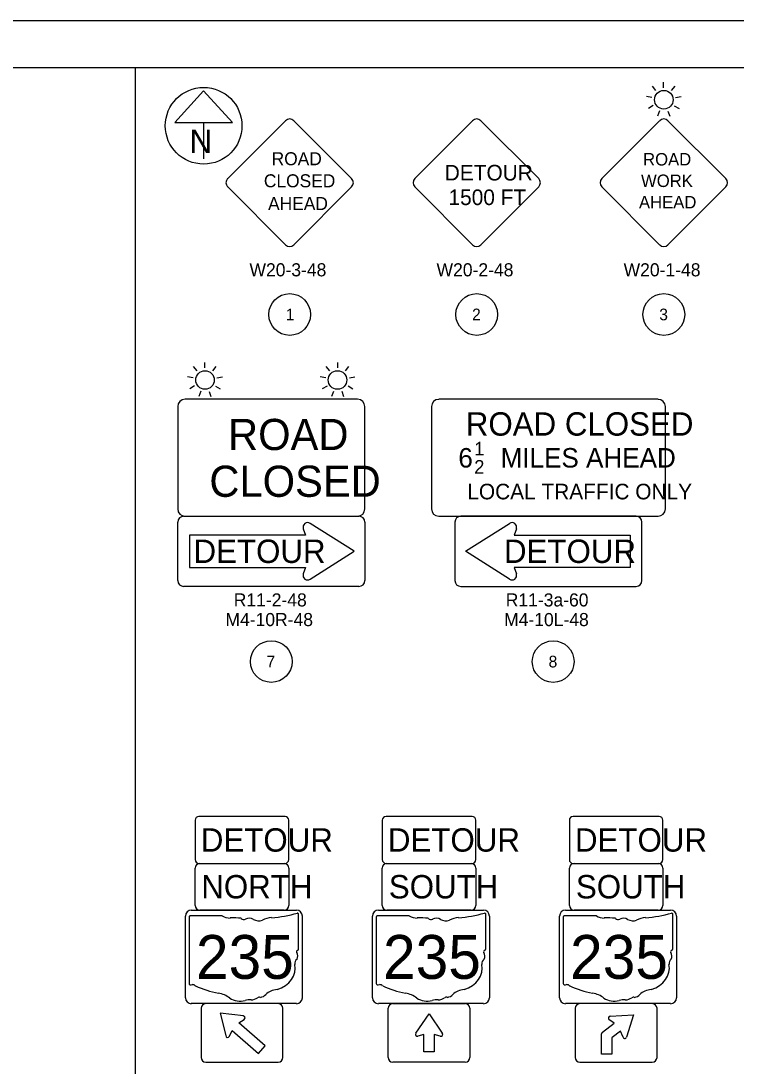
# Model space of a CAD drawing. Extents: x 632.2 to 666.2, y -36.3 to -14.3.
# Drawn here: x 649.19 to 656.83, y -25.48 to -14.3 of the extents above; entities that cross this region are included whole.
import ezdxf

# ---------------------------------------------------------------- set-up
doc = ezdxf.new("R2010")
doc.units = 0
for name, color, linetype in [('Default', 7, 'Continuous'), ('MT_P_Cells', 7, 'Continuous'), ('SH_Border', 7, 'Continuous'), ('SH_Cut_Line', 7, 'Continuous'), ('SH_Masking', 7, 'Continuous'), ('SH_Text', 7, 'Continuous'), ('SN_P_Signs', 7, 'Continuous'), ('SN_P_Text', 7, 'Continuous')]:
    doc.layers.add(name, color=color, linetype=linetype)

msp = doc.modelspace()

# ---------------------------------------------------------------- linework, layer by layer
at = {"layer": 'Default'}
for centre in [(652.061, -17.441), (654.061, -17.441), (656.061, -17.441), (651.864, -21.151), (654.878, -21.151)]:
    msp.add_circle(centre, 0.223, dxfattribs=at)
at = {"layer": 'MT_P_Cells'}
for p, q in [((656.059, -15.016), (656.059, -14.956)), ((655.977, -15.046), (655.939, -15.001)), ((656.143, -15.045), (656.181, -14.999)), ((655.934, -15.122), (655.875, -15.112)), ((656.187, -15.122), (656.246, -15.111)), ((655.948, -15.208), (655.897, -15.238)), ((656.015, -15.265), (655.995, -15.321)), ((656.104, -15.266), (656.124, -15.322)), ((656.172, -15.209), (656.224, -15.239)), ((651.154, -18.012), (651.154, -17.953)), ((652.574, -18.012), (652.574, -17.953)), ((651.072, -18.043), (651.034, -17.998)), ((651.238, -18.042), (651.276, -17.996)), ((652.491, -18.042), (652.452, -17.996)), ((652.656, -18.043), (652.694, -17.998)), ((651.029, -18.119), (650.97, -18.109)), ((651.043, -18.205), (650.992, -18.235)), ((651.267, -18.206), (651.319, -18.236)), ((651.282, -18.118), (651.341, -18.108)), ((652.446, -18.118), (652.387, -18.108)), ((652.461, -18.206), (652.41, -18.236)), ((652.685, -18.205), (652.736, -18.235)), ((652.699, -18.119), (652.758, -18.109)), ((651.11, -18.262), (651.09, -18.318)), ((651.199, -18.263), (651.219, -18.319)), ((652.529, -18.263), (652.509, -18.319)), ((652.618, -18.262), (652.638, -18.318))]:
    msp.add_line(p, q, dxfattribs=at)
for centre in [(656.061, -15.145), (651.156, -18.141), (652.572, -18.141)]:
    msp.add_circle(centre, 0.0992, dxfattribs=at)
at = {"layer": 'SH_Border'}
msp.add_lwpolyline([(633.687, -14.802), (665.687, -14.802), (665.687, -35.802), (633.687, -35.802)], close=True, dxfattribs=at)
at = {"layer": 'SH_Cut_Line'}
msp.add_lwpolyline([(632.187, -36.302), (666.187, -36.302), (666.187, -14.302), (632.187, -14.302)], close=True, dxfattribs=at)
at = {"layer": 'SH_Masking'}
msp.add_circle((651.141, -15.423), 0.41, dxfattribs=at)
at = {"layer": 'SH_Text'}
for p, q in [((650.412, -35.802), (650.412, -14.802)), ((651.141, -15.049), (650.833, -15.39)), ((651.449, -15.39), (651.141, -15.049)), ((650.833, -15.39), (651.449, -15.39)), ((651.141, -15.39), (651.141, -15.777))]:
    msp.add_line(p, q, dxfattribs=at)
for points in [[(651.398, -15.988), (652.016, -15.369)], [(652.105, -15.369), (652.723, -15.988)], [(652.016, -16.695), (651.398, -16.076)], [(652.723, -16.076), (652.105, -16.695)]]:
    msp.add_lwpolyline(points, dxfattribs=at)
msp.add_circle((651.141, -15.423), 0.41, dxfattribs=at)
for centre, start, end in [((652.061, -15.413), 45, 135), ((651.442, -16.032), 135, 225), ((652.679, -16.032), 315, 45), ((652.061, -16.651), 225, 315)]:
    msp.add_arc(centre, 0.0625, start, end, dxfattribs=at)
at = {"layer": 'SN_P_Signs'}
for p, q in [((652.206, -19.731), (652.229, -19.801)), ((652.749, -19.972), (652.281, -19.674)), ((653.942, -19.972), (654.41, -19.674)), ((654.485, -19.731), (654.462, -19.801)), ((652.229, -19.801), (650.989, -19.801)), ((650.989, -19.801), (650.989, -20.144)), ((654.462, -19.801), (655.702, -19.801)), ((655.702, -19.801), (655.702, -20.144)), ((652.281, -20.271), (652.749, -19.972)), ((654.41, -20.271), (653.942, -19.972)), ((650.989, -20.144), (652.229, -20.144)), ((652.229, -20.144), (652.206, -20.214)), ((655.702, -20.144), (654.462, -20.144)), ((654.462, -20.144), (654.485, -20.214)), ((651.101, -23.308), (652.001, -23.308)), ((653.101, -23.308), (654.001, -23.308)), ((655.101, -23.308), (656.001, -23.308)), ((651.051, -23.758), (651.051, -23.358)), ((652.051, -23.358), (652.051, -23.758)), ((653.051, -23.758), (653.051, -23.358)), ((654.051, -23.358), (654.051, -23.758)), ((655.051, -23.758), (655.051, -23.358)), ((656.051, -23.358), (656.051, -23.758)), ((650.985, -23.882), (650.985, -24.594)), ((651.34, -23.87), (650.997, -23.87)), ((652.001, -23.808), (651.101, -23.808)), ((652.157, -24.224), (652.157, -23.852)), ((652.985, -23.882), (652.985, -24.594)), ((653.34, -23.87), (652.997, -23.87)), ((654.001, -23.808), (653.101, -23.808)), ((654.157, -24.224), (654.157, -23.852)), ((654.985, -23.882), (654.985, -24.594)), ((655.34, -23.87), (654.997, -23.87)), ((656.001, -23.808), (655.101, -23.808)), ((656.157, -24.224), (656.157, -23.852)), ((652.157, -24.224), (652.157, -24.224)), ((654.157, -24.224), (654.157, -24.224)), ((656.157, -24.224), (656.157, -24.224)), ((651.113, -24.858), (651.113, -25.383)), ((651.938, -24.808), (651.163, -24.808)), ((651.566, -24.94), (651.316, -24.91)), ((651.316, -24.91), (651.377, -25.15)), ((651.988, -25.383), (651.988, -24.858)), ((653.113, -25.383), (653.113, -24.858)), ((653.163, -24.808), (653.938, -24.808)), ((653.988, -24.858), (653.988, -25.383)), ((655.113, -24.858), (655.113, -25.383)), ((655.938, -24.808), (655.163, -24.808)), ((655.988, -25.383), (655.988, -24.858)), ((651.517, -25.013), (651.574, -24.978)), ((651.798, -25.26), (651.517, -25.013)), ((651.566, -24.94), (651.566, -24.94)), ((653.408, -25.125), (653.551, -24.918)), ((653.551, -24.918), (653.69, -25.122)), ((655.404, -25.114), (655.53, -25.015)), ((655.53, -25.015), (655.474, -24.977)), ((655.488, -24.942), (655.738, -24.926)), ((655.488, -24.942), (655.488, -24.942)), ((655.738, -24.926), (655.663, -25.166)), ((651.417, -25.157), (651.445, -25.095)), ((651.445, -25.095), (651.726, -25.342)), ((653.496, -25.137), (653.432, -25.157)), ((653.496, -25.324), (653.496, -25.137)), ((653.669, -25.157), (653.605, -25.137)), ((653.605, -25.137), (653.605, -25.324)), ((655.394, -25.348), (655.394, -25.132)), ((655.597, -25.101), (655.51, -25.17)), ((655.622, -25.16), (655.597, -25.101)), ((655.504, -25.182), (655.504, -25.348)), ((651.726, -25.342), (651.798, -25.26)), ((653.605, -25.324), (653.496, -25.324)), ((655.504, -25.348), (655.394, -25.348)), ((651.163, -25.433), (651.938, -25.433)), ((653.938, -25.433), (653.163, -25.433)), ((655.163, -25.433), (655.938, -25.433))]:
    msp.add_line(p, q, dxfattribs=at)
for points in [[(653.398, -15.988), (654.016, -15.369)], [(654.105, -15.369), (654.723, -15.988)], [(655.398, -15.988), (656.016, -15.369)], [(656.105, -15.369), (656.723, -15.988)], [(654.016, -16.695), (653.398, -16.076)], [(654.723, -16.076), (654.105, -16.695)], [(656.016, -16.695), (655.398, -16.076)], [(656.723, -16.076), (656.105, -16.695)], [(650.864, -18.426), (650.864, -19.519)], [(652.786, -18.347), (650.942, -18.347)], [(652.864, -19.519), (652.864, -18.426)], [(653.577, -18.426), (653.577, -19.519)], [(655.999, -18.347), (653.655, -18.347)], [(656.077, -19.519), (656.077, -18.426)], [(650.864, -20.285), (650.864, -19.66)], [(650.927, -19.597), (652.802, -19.597)], [(650.942, -19.597), (652.786, -19.597)], [(652.864, -19.66), (652.864, -20.285)], [(653.655, -19.597), (655.999, -19.597)], [(653.827, -19.66), (653.827, -20.285)], [(655.765, -19.597), (653.89, -19.597)], [(655.827, -20.285), (655.827, -19.66)], [(652.802, -20.347), (650.927, -20.347)], [(653.89, -20.347), (655.765, -20.347)], [(651.051, -22.848), (651.051, -23.268)], [(652.011, -22.808), (651.091, -22.808)], [(652.051, -23.268), (652.051, -22.848)], [(653.051, -22.848), (653.051, -23.268)], [(654.011, -22.808), (653.091, -22.808)], [(654.051, -23.268), (654.051, -22.848)], [(655.051, -22.848), (655.051, -23.268)], [(656.011, -22.808), (655.091, -22.808)], [(656.051, -23.268), (656.051, -22.848)], [(651.091, -23.308), (652.011, -23.308)], [(653.091, -23.308), (654.011, -23.308)], [(655.091, -23.308), (656.011, -23.308)], [(650.946, -24.746), (650.946, -23.871)], [(651.009, -23.808), (652.134, -23.808)], [(652.196, -23.871), (652.196, -24.746)], [(652.946, -24.746), (652.946, -23.871)], [(653.009, -23.808), (654.134, -23.808)], [(654.196, -23.871), (654.196, -24.746)], [(654.946, -24.746), (654.946, -23.871)], [(655.009, -23.808), (656.134, -23.808)], [(656.196, -23.871), (656.196, -24.746)], [(652.134, -24.808), (651.009, -24.808)], [(654.134, -24.808), (653.009, -24.808)], [(656.134, -24.808), (655.009, -24.808)]]:
    msp.add_lwpolyline(points, dxfattribs=at)
for centre, radius, start, end in [((654.061, -15.413), 0.0625, 45, 135), ((656.061, -15.413), 0.0625, 45, 135), ((653.442, -16.032), 0.0625, 135, 225), ((654.679, -16.032), 0.0625, 315, 45), ((655.442, -16.032), 0.0625, 135, 225), ((656.679, -16.032), 0.0625, 315, 45), ((654.061, -16.651), 0.0625, 225, 315), ((656.061, -16.651), 0.0625, 225, 315), ((650.942, -18.426), 0.0783, 90, 180), ((652.786, -18.426), 0.0783, 0, 90), ((653.655, -18.426), 0.0781, 90, 180), ((655.999, -18.426), 0.0781, 0, 90), ((650.942, -19.519), 0.0783, 180, 270), ((652.786, -19.519), 0.0783, 270, 0), ((653.655, -19.519), 0.0781, 180, 270), ((655.999, -19.519), 0.0781, 270, 0), ((650.927, -19.66), 0.0625, 90, 180), ((652.802, -19.66), 0.0625, 0, 90), ((653.89, -19.66), 0.0625, 90, 180), ((655.765, -19.66), 0.0625, 0, 90), ((652.254, -19.716), 0.05, 57.4891, 197.8189), ((654.437, -19.716), 0.05, 342.1811, 122.5109), ((652.254, -20.229), 0.05, 162.1811, 302.5109), ((654.437, -20.229), 0.05, 237.4891, 17.8189), ((650.927, -20.285), 0.0625, 180, 270), ((652.802, -20.285), 0.0625, 270, 360), ((653.89, -20.285), 0.0625, 180, 270), ((655.765, -20.285), 0.0625, 270, 0), ((651.091, -22.848), 0.04, 90, 180), ((652.011, -22.848), 0.04, 0, 90), ((653.091, -22.848), 0.04, 90, 180), ((654.011, -22.848), 0.04, 0, 90), ((655.091, -22.848), 0.04, 90, 180), ((656.011, -22.848), 0.04, 0, 90), ((651.091, -23.268), 0.04, 180, 270), ((651.101, -23.358), 0.05, 90, 180), ((652.001, -23.358), 0.05, 0, 90), ((652.011, -23.268), 0.04, 270, 0), ((653.091, -23.268), 0.04, 180, 270), ((653.101, -23.358), 0.05, 90, 180), ((654.001, -23.358), 0.05, 0, 90), ((654.011, -23.268), 0.04, 270, 0), ((655.091, -23.268), 0.04, 180, 270), ((655.101, -23.358), 0.05, 90, 180), ((656.001, -23.358), 0.05, 0, 90), ((656.011, -23.268), 0.04, 270, 0), ((651.101, -23.758), 0.05, 180, 270), ((652.001, -23.758), 0.05, 270, 0), ((653.101, -23.758), 0.05, 180, 270), ((654.001, -23.758), 0.05, 270, 0), ((655.101, -23.758), 0.05, 180, 270), ((656.001, -23.758), 0.05, 270, 0), ((651.009, -23.871), 0.0625, 90, 180), ((652.134, -23.871), 0.0625, 0, 90), ((653.009, -23.871), 0.0625, 90, 180), ((654.134, -23.871), 0.0625, 0, 90), ((655.009, -23.871), 0.0625, 90, 180), ((656.134, -23.871), 0.0625, 0, 90), ((651.009, -24.746), 0.0625, 180, 270), ((652.134, -24.746), 0.0625, 270, 0), ((653.009, -24.746), 0.0625, 180, 270), ((654.134, -24.746), 0.0625, 270, 0), ((655.009, -24.746), 0.0625, 180, 270), ((656.134, -24.746), 0.0625, 270, 0), ((651.163, -24.858), 0.05, 90, 180), ((651.938, -24.858), 0.05, 0, 90), ((653.163, -24.858), 0.05, 90, 180), ((653.938, -24.858), 0.05, 0, 90), ((655.163, -24.858), 0.05, 90, 180), ((655.938, -24.858), 0.05, 0, 90), ((651.563, -24.96), 0.0208, 301.5367, 83.3301), ((655.489, -24.963), 0.0209, 93.5999, 225.0001), ((653.426, -25.137), 0.0209, 145.4112, 287.2046), ((653.676, -25.137), 0.0209, 252.7954, 45.0096), ((655.418, -25.132), 0.0234, 127.7857, 180), ((651.398, -25.148), 0.0208, 183.7317, 335.9459), ((655.519, -25.182), 0.0156, 127.3494, 180), ((655.643, -25.16), 0.0209, 180.0509, 342.5804), ((651.163, -25.383), 0.05, 180, 270), ((651.938, -25.383), 0.05, 270, 360), ((653.163, -25.383), 0.05, 180, 270), ((653.938, -25.383), 0.05, 270, 0), ((655.163, -25.383), 0.05, 180, 270), ((655.938, -25.383), 0.05, 270, 360)]:
    msp.add_arc(centre, radius, start, end, dxfattribs=at)
for centre, major_axis, start_param, end_param in [((650.999, -23.881), (0.0136, 0), 1.712693, 3.28349), ((651.422, -23.787), (0.132, 0), 4.042523, 4.731795), ((651.465, -24.269), (0.473, 0), 1.404758, 1.657858), ((651.573, -23.877), (0.038, 0), 3.836095, 5.185415), ((651.628, -23.959), (0.079, 0), 0.950623, 2.079405), ((651.73, -23.846), (0.095, 0), 4.081561, 5.145723), ((651.898, -24.087), (0.25, 0), 1.699011, 2.107814), ((651.74, -22.9), (1.243, 0), 4.814394, 5.042369), ((652.144, -23.851), (0.013, 0), 6.141152, 7.989035), ((652.999, -23.881), (0.0136, 0), 1.712693, 3.28349), ((653.422, -23.787), (0.132, 0), 4.042523, 4.731795), ((653.465, -24.269), (0.473, 0), 1.404758, 1.657858), ((653.573, -23.877), (0.038, 0), 3.836095, 5.185415), ((653.628, -23.959), (0.079, 0), 0.950623, 2.079405), ((653.73, -23.846), (0.095, 0), 4.081561, 5.145723), ((653.898, -24.087), (0.25, 0), 1.699011, 2.107814), ((653.74, -22.9), (1.243, 0), 4.814394, 5.042369), ((654.144, -23.851), (0.013, 0), 6.141152, 7.989035), ((654.999, -23.881), (0.0136, 0), 1.712693, 3.28349), ((655.422, -23.787), (0.132, 0), 4.042523, 4.731795), ((655.465, -24.269), (0.473, 0), 1.404758, 1.657858), ((655.573, -23.877), (0.038, 0), 3.836095, 5.185415), ((655.628, -23.959), (0.079, 0), 0.950623, 2.079405), ((655.73, -23.846), (0.095, 0), 4.081561, 5.145723), ((655.898, -24.087), (0.25, 0), 1.699011, 2.107814), ((655.74, -22.9), (1.243, 0), 4.814394, 5.042369), ((656.144, -23.851), (0.013, 0), 6.141152, 7.989035), ((652.154, -24.252), (0.0202, 0), 1.883978, 3.671073), ((652.143, -24.226), (0.014, 0), 5.05454, 6.418171), ((654.154, -24.252), (0.0202, 0), 1.883978, 3.671073), ((654.143, -24.226), (0.014, 0), 5.05454, 6.418171), ((656.154, -24.252), (0.0202, 0), 1.883978, 3.671073), ((656.143, -24.226), (0.014, 0), 5.05454, 6.418171), ((652.204, -24.38), (0.0882, 0), 2.387724, 3.262537), ((652.026, -24.299), (0.121, 0), 5.934695, 6.695948), ((654.204, -24.38), (0.0882, 0), 2.387724, 3.262537), ((654.026, -24.299), (0.121, 0), 5.934695, 6.695948), ((656.204, -24.38), (0.0882, 0), 2.387724, 3.262537), ((656.026, -24.299), (0.121, 0), 5.934695, 6.695948), ((651.809, -24.428), (0.311, 0), 5.101752, 6.440018), ((653.809, -24.428), (0.311, 0), 5.101752, 6.440018), ((655.809, -24.428), (0.311, 0), 5.101752, 6.440018), ((650.999, -24.595), (0.0137, 0), 3.00124, 4.508301), ((651.001, -24.522), (0.105, 0), 4.665946, 4.897461), ((651.022, -24.635), (0.0377, 0), 0.519207, 1.627899), ((651.498, -23.995), (0.897, 0), 4.195997, 4.488961), ((651.94, -24.793), (0.17, 0), 1.647645, 2.488434), ((652.999, -24.595), (0.0137, 0), 3.00124, 4.508301), ((653.001, -24.522), (0.105, 0), 4.665946, 4.897461), ((653.022, -24.635), (0.0377, 0), 0.519207, 1.627899), ((653.498, -23.995), (0.897, 0), 4.195997, 4.488961), ((653.94, -24.793), (0.17, 0), 1.647645, 2.488434), ((654.999, -24.595), (0.0137, 0), 3.00124, 4.508301), ((655.001, -24.522), (0.105, 0), 4.665946, 4.897461), ((655.022, -24.635), (0.0377, 0), 0.519207, 1.627899), ((655.498, -23.995), (0.897, 0), 4.195997, 4.488961), ((655.94, -24.793), (0.17, 0), 1.647645, 2.488434), ((651.23, -24.913), (0.281, 0), 0.823519, 1.323587), ((651.534, -24.638), (0.178, 0), 4.026481, 4.996735), ((651.637, -24.884), (0.146, 0), 1.495662, 1.94098), ((651.65, -24.691), (0.0949, 0), 4.691044, 5.507374), ((651.736, -24.76), (0.0267, 0), 1.147584, 2.315152), ((651.725, -24.663), (0.1, 0), 4.937069, 5.64225), ((653.23, -24.913), (0.281, 0), 0.823519, 1.323587), ((653.534, -24.638), (0.178, 0), 4.026481, 4.996735), ((653.637, -24.884), (0.146, 0), 1.495662, 1.94098), ((653.65, -24.691), (0.0949, 0), 4.691044, 5.507374), ((653.736, -24.76), (0.0267, 0), 1.147584, 2.315152), ((653.725, -24.663), (0.1, 0), 4.937069, 5.64225), ((655.23, -24.913), (0.281, 0), 0.823519, 1.323587), ((655.534, -24.638), (0.178, 0), 4.026481, 4.996735), ((655.637, -24.884), (0.146, 0), 1.495662, 1.94098), ((655.65, -24.691), (0.0949, 0), 4.691044, 5.507374), ((655.736, -24.76), (0.0267, 0), 1.147584, 2.315152), ((655.725, -24.663), (0.1, 0), 4.937069, 5.64225)]:
    msp.add_ellipse(centre, major_axis=major_axis, ratio=0.8, start_param=start_param, end_param=end_param, dxfattribs=at)

# ---------------------------------------------------------------- texts
at = {"layer": 'Default'}
for s, p in [('1', (652.019, -17.503)), ('2', (654.011, -17.503)), ('3', (656.012, -17.503)), ('7', (651.812, -21.214)), ('8', (654.829, -21.214))]:
    msp.add_text(s, height=0.125, dxfattribs=at).set_placement(p)
at = {"layer": 'SH_Text'}
for s, height, p in [('N', 0.25, (650.99, -15.714)), ('ROAD', 0.1389, (651.868, -15.845)), ('CLOSED', 0.1389, (651.785, -16.081)), ('AHEAD', 0.1389, (651.83, -16.324))]:
    msp.add_text(s, height=height, dxfattribs=at).set_placement(p)
at = {"layer": 'SN_P_Signs'}
for s, height, p in [('ROAD', 0.1333, (655.839, -15.848)), ('DETOUR', 0.1667, (653.719, -16.008)), ('WORK', 0.1333, (655.817, -16.078)), ('1500 FT', 0.1667, (653.759, -16.271)), ('AHEAD', 0.1333, (655.795, -16.307)), ('ROAD CLOSED', 0.25, (653.944, -18.736)), ('ROAD', 0.3333, (651.402, -18.89)), ('6 ', 0.2083, (653.864, -19.077)), ('1', 0.146, (654.034, -18.948)), ('MILES AHEAD', 0.20833, (654.316, -19.077)), ('CLOSED', 0.3333, (651.202, -19.39)), ('2', 0.146, (654.034, -19.143)), ('LOCAL TRAFFIC ONLY', 0.16667, (653.96, -19.417)), ('DETOUR', 0.25, (651.033, -20.097)), ('DETOUR', 0.25, (654.352, -20.097)), ('DETOUR', 0.25, (651.111, -23.183)), ('DETOUR', 0.25, (653.111, -23.183)), ('DETOUR', 0.25, (655.111, -23.183)), ('NORTH', 0.25, (651.116, -23.683)), ('SOUTH', 0.25, (653.121, -23.683)), ('SOUTH', 0.25, (655.121, -23.683)), ('235', 0.4688, (651.059, -24.543)), ('235', 0.4688, (653.059, -24.543)), ('235', 0.4688, (655.059, -24.543))]:
    msp.add_text(s, height=height, dxfattribs=at).set_placement(p)
at = {"layer": 'SN_P_Text'}
for s, p in [('W20-3-48', (651.631, -17.033)), ('W20-2-48', (653.631, -17.033)), ('W20-1-48', (655.631, -17.033)), ('R11-2-48', (651.463, -20.562)), ('R11-3a-60', (654.371, -20.562)), ('M4-10R-48', (651.374, -20.772)), ('M4-10L-48', (654.353, -20.772))]:
    msp.add_text(s, height=0.14, dxfattribs=at).set_placement(p)

doc.saveas('drawing.dxf')
